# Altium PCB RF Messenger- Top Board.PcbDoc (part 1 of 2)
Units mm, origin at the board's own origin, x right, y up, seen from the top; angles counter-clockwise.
Board outline 60 x 85 mm, 2 copper layers (Top Layer, Bottom Layer), stack 1.569 mm thick; 38 components, 18 nets, 106 pads, 20 vias.
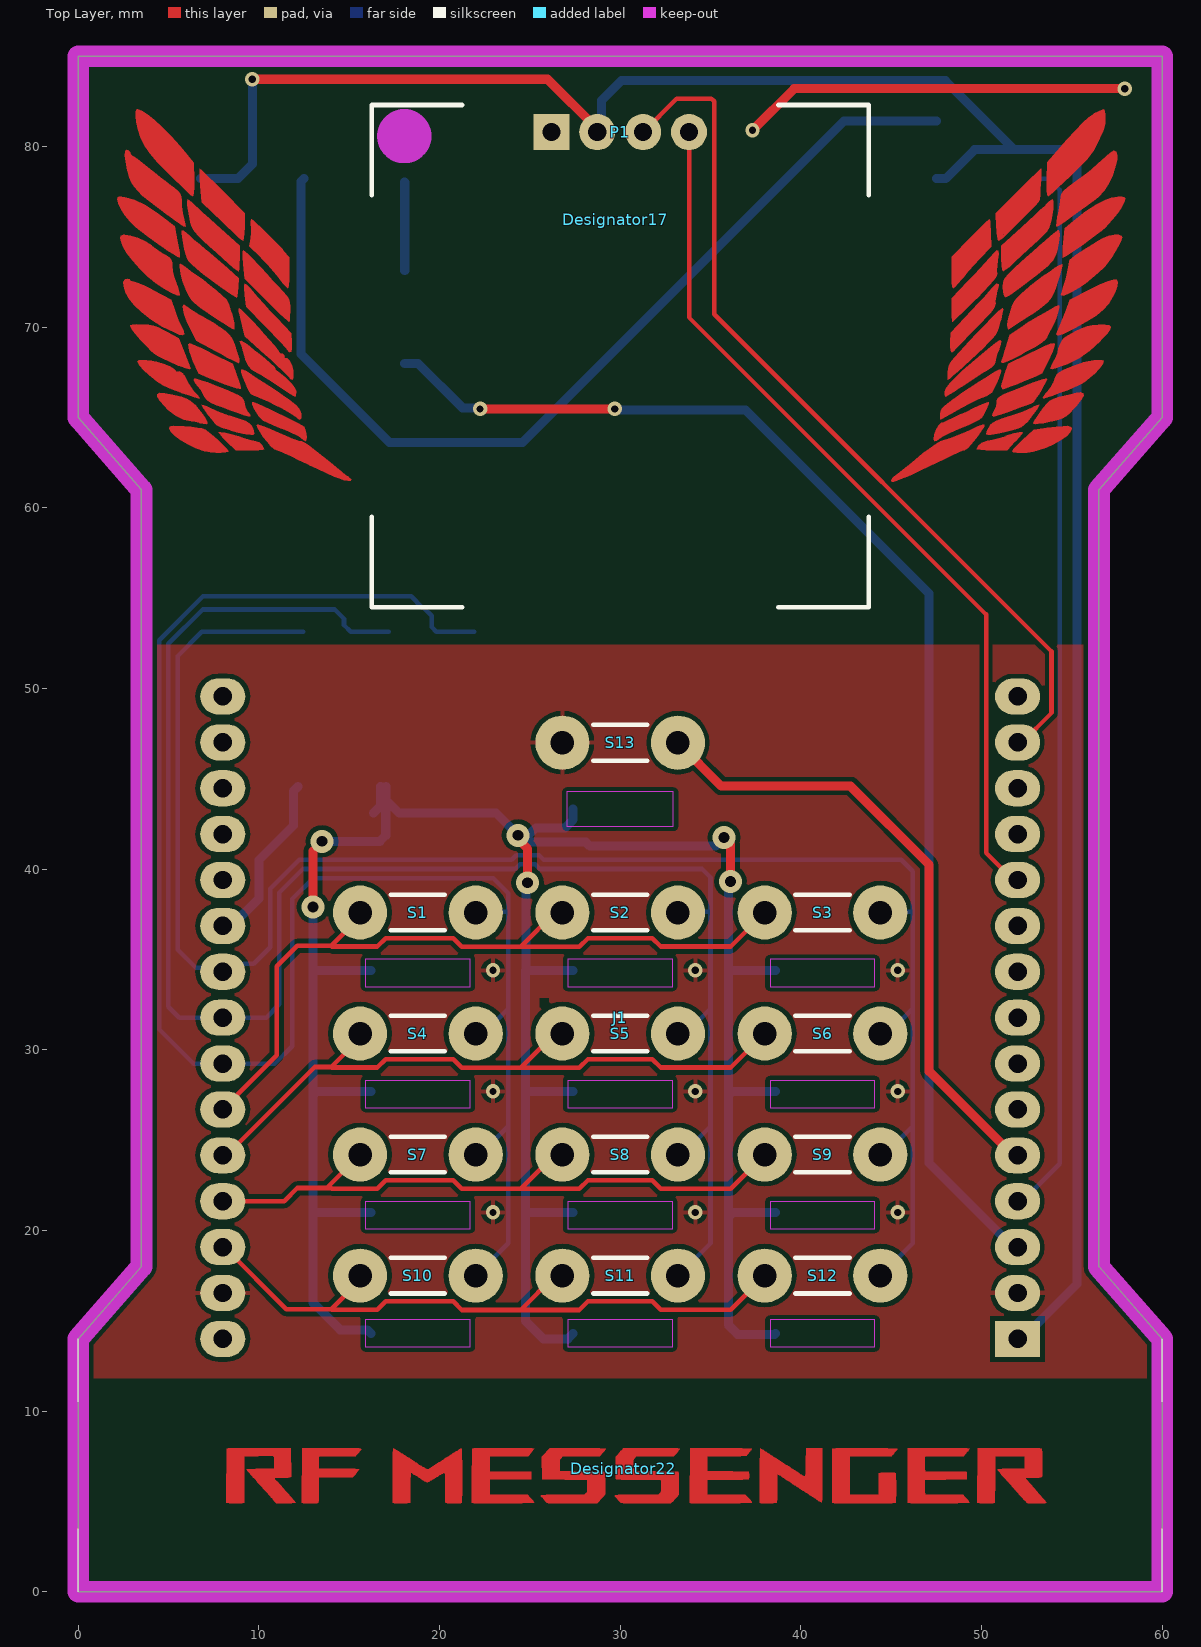
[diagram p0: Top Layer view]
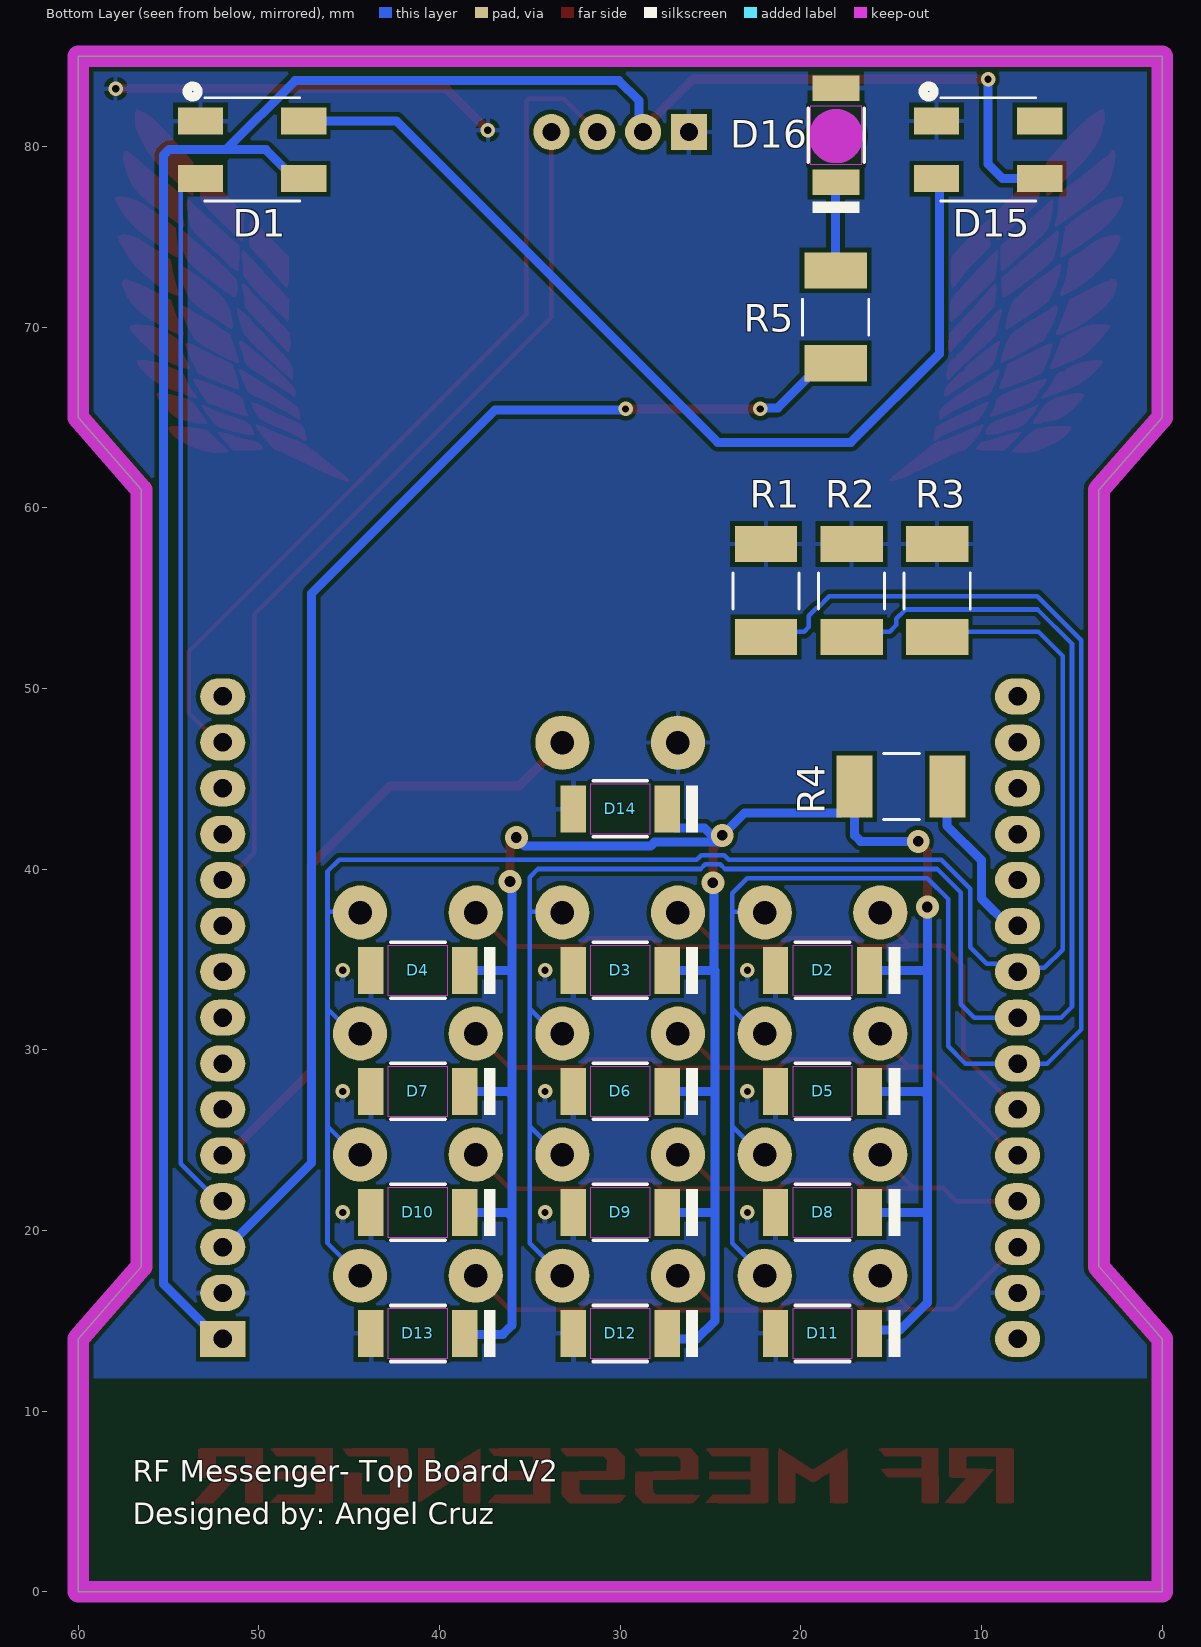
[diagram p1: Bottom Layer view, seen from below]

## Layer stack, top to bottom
Top Solder: solder mask 0.0254, SM-001, Dk 4
Top Layer: signal copper 0.035
Dielectric 1: core 1.4986, Core-043, Dk 4.3
Bottom Layer: signal copper 0.035
Bottom Solder: solder mask 0.0254, SM-001, Dk 4

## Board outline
0,0 0,14 3.5,18 3.5,61 0,65 0,85 60,85 60,65 56.5,61 56.5,18 60,14 60,0

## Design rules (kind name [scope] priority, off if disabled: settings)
Clearance [All] p1: gap=0.254 ignorepadtopadclearanceinfootprint=FALSE except(0: Arc-Hole Track-Hole SMDPad-Hole THPad-Hole Via-Hole Fill-Hole Poly-Hole Region-Hole Text-Hole)
PolygonConnect [All] p1: connectstyle=Relief reliefconductorwidth=0.254 reliefentries=4 polygonreliefangle="90 Angle" airgapwidth=0.254
RoutingVias "RoutingVias 2" [All] p1: holewidth=0.4 width=0.8 viastyle="Through Hole" minholewidth=0.4 minwidth=0.8 maxholewidth=0.711 maxwidth=1.27
RoutingVias [All] p2: holewidth=0.711 width=1.27 viastyle="Through Hole" minholewidth=0.711 minwidth=1.27 maxholewidth=0.711 maxwidth=1.27
SolderMaskExpansion [All] p1: expansion=0.102 istentingtop=FALSE
Width "Width 2" [All] p1: maxlimit=0.5 minlimit=0.25 preferedwidth=0.25
Width [All] p2: maxlimit=0.254 minlimit=0.254 preferedwidth=0.254
30 further rules are at their usual default settings.

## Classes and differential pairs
component class "RF Messenger- Top Board": D1 D2 D3 D4 D5 D6 D7 D8 D9 D10 D11 D12 D13 D14 D15 D16 J1 P1 R1 R2 R3 R4 R5 S1 S2 S3 S4 S5 S6 S7 S8 S9 S10 S11 S12 S13

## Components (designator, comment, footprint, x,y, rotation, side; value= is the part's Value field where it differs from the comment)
D1 "1655" LED_1655_ADA 50.371,79.821 r180 bottom
D2 "LED 2" XZDGK45WT-9 18.8,34.4 r0 bottom
D3 "LED 2" XZDGK45WT-9 30,34.4 r0 bottom
D4 "LED 2" XZDGK45WT-9 41.2,34.4 r0 bottom
D5 "LED 2" XZDGK45WT-9 18.8,27.7 r0 bottom
D6 "LED 2" XZDGK45WT-9 30,27.7 r0 bottom
D7 "LED 2" XZDGK45WT-9 41.2,27.7 r0 bottom
D8 "LED 2" XZDGK45WT-9 18.8,21 r0 bottom
D9 "LED 2" XZDGK45WT-9 30,21 r0 bottom
D10 "LED 2" XZDGK45WT-9 41.2,21 r0 bottom
D11 "LED 2" XZDGK45WT-9 18.8,14.3 r0 bottom
D12 "LED 2" XZDGK45WT-9 30,14.3 r0 bottom
D13 "LED 2" XZDGK45WT-9 41.2,14.3 r0 bottom
D14 "LED 2" XZDGK45WT-9 30,43.338 r0 bottom
D15 "1655" LED_1655_ADA 9.629,79.821 r180 bottom
D16 "LED 2" XZDGK45WT-9 18.05,80.625 r90 bottom
Designator17 "Comment" "Wings Artwork" 29.763,75.97 r0 top
Designator22 "Comment" "LOGO 4" 30.2,6.825 r0 top
J1 "Connector 2x15" "RF Messenger Connector Headers - duplicate" 52,14 r0 top locked
P1 "Header 4" OLED 26.19,80.8 r0 top locked
R1 "2k" "Resistor 1812_PAN-M" 21.93,55.42 r90 bottom
R2 "2k" "Resistor 1812_PAN-M" 17.193,55.42 r90 bottom
R3 "2k" "Resistor 1812_PAN-M" 12.456,55.42 r90 bottom
R4 "1K" "Resistor 1812_PAN-M" 14.45,44.575 r0 bottom
R5 "390" "Resistor 1812_PAN-M" 18.075,70.575 r90 bottom
S1 "Switch" "Tactile Switch (PTS636 SP50 LFS) THT" 18.8,37.6 r0 top
S2 "Switch" "Tactile Switch (PTS636 SP50 LFS) THT" 30,37.6 r0 top
S3 "Switch" "Tactile Switch (PTS636 SP50 LFS) THT" 41.2,37.6 r0 top
S4 "Switch" "Tactile Switch (PTS636 SP50 LFS) THT" 18.8,30.9 r0 top
S5 "Switch" "Tactile Switch (PTS636 SP50 LFS) THT" 30,30.9 r0 top
S6 "Switch" "Tactile Switch (PTS636 SP50 LFS) THT" 41.2,30.9 r0 top
S7 "Switch" "Tactile Switch (PTS636 SP50 LFS) THT" 18.8,24.2 r0 top
S8 "Switch" "Tactile Switch (PTS636 SP50 LFS) THT" 30,24.2 r0 top
S9 "Switch" "Tactile Switch (PTS636 SP50 LFS) THT" 41.2,24.2 r0 top
S10 "Switch" "Tactile Switch (PTS636 SP50 LFS) THT" 18.8,17.5 r0 top
S11 "Switch" "Tactile Switch (PTS636 SP50 LFS) THT" 30,17.5 r0 top
S12 "Switch" "Tactile Switch (PTS636 SP50 LFS) THT" 41.2,17.5 r0 top
S13 "Switch" "Tactile Switch (PTS636 SP50 LFS) THT" 30,47 r180 top

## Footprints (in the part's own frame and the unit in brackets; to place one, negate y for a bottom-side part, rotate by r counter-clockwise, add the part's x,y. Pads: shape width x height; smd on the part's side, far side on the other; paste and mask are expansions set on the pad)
LED_1655_ADA [mm]
  rect 2.5x1.5 smd paste+0: 1(-2.857,1.6) 2(-2.857,-1.6) 3(2.857,-1.6) 4(2.857,1.6)
  silkscreen extent -3.6,-2.83 2.63,3.52
"LOGO 4" [mm]
  Top Layer region: 22.245,1.118 22.469,1.117 22.657,1.116 22.81,1.114 22.932,1.112 23.023,1.109 23.085,1.105 23.119,1.101 23.128,1.098 23.135,1.084 23.142,1.055 23.147,1.006 23.15,0.935 23.153,0.836 23.155,0.706 23.156,0.542 23.156,0.34 23.156,0.316 23.156,-0.442 23.109,-0.475 23.085,-0.487 23.049,-0.496 22.993,-0.502 22.912,-0.505 22.801,-0.507 22.654,-0.508 22.512,-0.508 22.406,-0.51 22.333,-0.513 22.285,-0.517 22.259,-0.524 22.248,-0.534 22.246,-0.541 22.26,-0.585 22.273,-0.602 22.302,-0.634 22.353,-0.69 22.419,-0.765 22.494,-0.849 22.572,-0.937 22.645,-1.021 22.669,-1.048 22.737,-1.125 22.808,-1.205 22.866,-1.27 22.976,-1.391 23.08,-1.508 23.175,-1.616 23.256,-1.711 23.322,-1.789 23.367,-1.845 23.388,-1.876 23.389,-1.879 23.371,-1.897 23.326,-1.912 23.323,-1.913 23.278,-1.918 23.199,-1.921 23.095,-1.924 22.974,-1.925 22.845,-1.926 22.716,-1.925 22.594,-1.924 22.489,-1.921 22.409,-1.918 22.362,-1.913 22.36,-1.913 22.309,-1.886 22.238,-1.824 22.151,-1.73 22.083,-1.653 22.02,-1.581 21.97,-1.525 21.95,-1.502 21.897,-1.443 21.845,-1.383 21.805,-1.338 21.748,-1.275 21.685,-1.205 21.676,-1.195 21.6,-1.112 21.516,-1.017 21.442,-0.933 21.385,-0.868 21.338,-0.814 21.308,-0.78 21.303,-0.775 21.278,-0.747 21.23,-0.695 21.166,-0.624 21.092,-0.54 21.012,-0.452 20.934,-0.364 20.863,-0.283 20.804,-0.217 20.78,-0.189 20.729,-0.129 20.703,-0.091 20.698,-0.068 20.711,-0.051 20.716,-0.048 20.737,-0.04 20.78,-0.034 20.849,-0.029 20.946,-0.026 21.076,-0.023 21.241,-0.022 21.444,-0.021 21.478,-0.021 22.205,-0.021 22.199,0.323 22.193,0.667 20.563,0.667 20.553,-0.613 20.542,-1.893 20.489,-1.907 20.446,-1.913 20.371,-1.918 20.271,-1.921 20.157,-1.922 20.035,-1.922 19.916,-1.921 19.806,-1.918 19.715,-1.914 19.652,-1.909 19.627,-1.904 19.579,-1.885 19.59,1.111 21.344,1.117 21.685,1.118 21.985,1.118
  Top Layer region: 18.281,1.118 18.493,1.117 18.671,1.116 18.817,1.115 18.932,1.113 19.02,1.11 19.082,1.106 19.12,1.102 19.136,1.098 19.137,1.097 19.14,1.082 19.131,1.059 19.104,1.023 19.056,0.967 18.986,0.891 18.955,0.855 18.911,0.8 18.884,0.767 18.814,0.677 17.769,0.677 17.562,0.677 17.367,0.676 17.189,0.675 17.032,0.674 16.899,0.672 16.796,0.67 16.725,0.667 16.693,0.665 16.692,0.664 16.679,0.654 16.67,0.632 16.664,0.59 16.66,0.523 16.659,0.426 16.658,0.295 16.659,0.173 16.663,0.062 16.668,-0.029 16.674,-0.092 16.679,-0.115 16.699,-0.169 17.817,-0.17 18.031,-0.17 18.232,-0.171 18.417,-0.173 18.582,-0.175 18.722,-0.177 18.834,-0.18 18.913,-0.183 18.955,-0.186 18.961,-0.187 18.975,-0.21 18.982,-0.261 18.983,-0.346 18.982,-0.404 18.976,-0.603 17.822,-0.614 17.606,-0.616 17.402,-0.619 17.215,-0.621 17.049,-0.623 16.908,-0.625 16.795,-0.627 16.715,-0.628 16.671,-0.63 16.663,-0.63 16.659,-0.655 16.657,-0.713 16.656,-0.797 16.657,-0.899 16.658,-1.01 16.661,-1.123 16.665,-1.228 16.669,-1.318 16.674,-1.384 16.679,-1.418 16.68,-1.42 16.686,-1.429 16.697,-1.437 16.715,-1.443 16.744,-1.448 16.788,-1.452 16.851,-1.455 16.935,-1.457 17.045,-1.459 17.184,-1.46 17.356,-1.46 17.563,-1.46 17.741,-1.461 18.78,-1.461 18.868,-1.551 18.977,-1.667 19.056,-1.757 19.108,-1.823 19.134,-1.867 19.136,-1.891 19.134,-1.893 19.109,-1.897 19.046,-1.901 18.949,-1.904 18.821,-1.907 18.666,-1.91 18.489,-1.913 18.293,-1.915 18.081,-1.917 17.859,-1.918 17.63,-1.92 17.398,-1.92 17.166,-1.921 16.939,-1.921 16.721,-1.921 16.515,-1.92 16.326,-1.919 16.157,-1.917 16.012,-1.915 15.895,-1.913 15.811,-1.91 15.762,-1.906 15.753,-1.904 15.705,-1.885 15.716,1.111 17.419,1.117 17.746,1.118 18.032,1.118
  Top Layer region: 13.305,1.119 13.544,1.118 13.779,1.117 14.009,1.116 14.227,1.114 14.432,1.111 14.618,1.109 14.782,1.106 14.921,1.102 15.03,1.098 15.106,1.094 15.145,1.089 15.149,1.087 15.143,1.053 15.13,1.034 15.103,1.004 15.059,0.952 15.008,0.889 14.953,0.823 14.902,0.763 14.868,0.725 14.823,0.678 13.671,0.672 12.52,0.667 12.52,-1.45 13.271,-1.456 13.448,-1.457 13.612,-1.457 13.759,-1.457 13.883,-1.456 13.98,-1.454 14.045,-1.452 14.071,-1.45 14.118,-1.439 14.118,-0.274 14.172,-0.253 14.215,-0.245 14.289,-0.239 14.386,-0.235 14.498,-0.233 14.618,-0.232 14.737,-0.234 14.847,-0.237 14.94,-0.242 15.008,-0.248 15.043,-0.257 15.045,-0.258 15.052,-0.286 15.058,-0.35 15.063,-0.445 15.067,-0.565 15.07,-0.705 15.072,-0.858 15.073,-1.019 15.072,-1.182 15.071,-1.341 15.069,-1.492 15.066,-1.627 15.062,-1.741 15.057,-1.829 15.051,-1.884 15.045,-1.901 15.02,-1.905 14.957,-1.909 14.859,-1.912 14.731,-1.915 14.575,-1.918 14.397,-1.92 14.2,-1.922 13.987,-1.924 13.763,-1.925 13.531,-1.925 13.296,-1.926 13.062,-1.926 12.831,-1.925 12.609,-1.925 12.398,-1.923 12.203,-1.922 12.028,-1.92 11.876,-1.917 11.752,-1.914 11.659,-1.911 11.601,-1.907 11.583,-1.904 11.536,-1.885 11.536,-0.408 11.536,-0.161 11.537,0.073 11.538,0.292 11.54,0.492 11.542,0.669 11.544,0.82 11.546,0.942 11.549,1.03 11.551,1.083 11.553,1.095 11.577,1.1 11.639,1.104 11.736,1.108 11.863,1.111 12.018,1.114 12.196,1.116 12.394,1.117 12.607,1.118 12.832,1.119 13.066,1.119
  Top Layer region: 159 vertices and 0 holes, not listed, extent 7.535,-1.92 10.982,1.111
  Top Layer region: 5.733,1.111 6.049,1.11 6.322,1.109 6.554,1.107 6.744,1.105 6.891,1.102 6.997,1.098 7.061,1.094 7.084,1.09 7.084,1.09 7.075,1.062 7.046,1.019 7.033,1.004 6.987,0.952 6.932,0.887 6.876,0.82 6.828,0.76 6.796,0.719 6.79,0.711 6.767,0.705 6.708,0.699 6.61,0.694 6.473,0.69 6.297,0.686 6.08,0.682 5.823,0.679 5.7,0.677 4.625,0.667 4.625,-0.159 5.755,-0.164 6.034,-0.166 6.271,-0.168 6.469,-0.171 6.629,-0.174 6.752,-0.178 6.839,-0.183 6.893,-0.188 6.914,-0.193 6.93,-0.227 6.941,-0.288 6.945,-0.366 6.944,-0.448 6.937,-0.522 6.925,-0.577 6.909,-0.601 6.882,-0.603 6.817,-0.606 6.717,-0.608 6.588,-0.61 6.432,-0.611 6.255,-0.613 6.059,-0.614 5.85,-0.614 5.771,-0.614 5.559,-0.615 5.358,-0.616 5.175,-0.617 5.011,-0.619 4.873,-0.621 4.763,-0.624 4.686,-0.627 4.645,-0.63 4.64,-0.632 4.63,-0.648 4.624,-0.687 4.619,-0.752 4.618,-0.848 4.618,-0.98 4.619,-1.049 4.625,-1.45 5.675,-1.455 6.726,-1.461 6.801,-1.54 6.909,-1.655 6.99,-1.743 7.045,-1.808 7.078,-1.853 7.091,-1.881 7.088,-1.894 7.065,-1.897 7.003,-1.9 6.907,-1.903 6.78,-1.905 6.626,-1.908 6.45,-1.91 6.254,-1.912 6.044,-1.914 5.822,-1.916 5.594,-1.918 5.361,-1.919 5.13,-1.92 4.903,-1.92 4.685,-1.921 4.478,-1.921 4.289,-1.92 4.119,-1.92 3.973,-1.919 3.855,-1.917 3.769,-1.915 3.719,-1.913 3.709,-1.911 3.662,-1.902 3.672,1.111 5.375,1.111
  Top Layer region: 1.84,1.122 2.106,1.121 2.334,1.12 2.527,1.119 2.687,1.118 2.817,1.116 2.919,1.113 2.995,1.11 3.049,1.106 3.081,1.102 3.095,1.097 3.096,1.095 3.088,1.065 3.053,1.01 2.997,0.938 2.925,0.854 2.844,0.767 2.756,0.677 0.702,0.677 0.615,0.573 0.528,0.469 0.534,0.155 0.54,-0.159 1.765,-0.164 2.055,-0.166 2.303,-0.168 2.512,-0.17 2.683,-0.173 2.817,-0.177 2.917,-0.181 2.982,-0.186 3.015,-0.191 3.02,-0.193 3.028,-0.209 3.035,-0.241 3.04,-0.295 3.044,-0.375 3.046,-0.484 3.048,-0.627 3.048,-0.808 3.048,-0.83 3.048,-1.443 2.947,-1.563 2.879,-1.642 2.799,-1.73 2.729,-1.804 2.61,-1.926 1.258,-1.925 1.021,-1.924 0.797,-1.923 0.587,-1.922 0.398,-1.92 0.231,-1.918 0.09,-1.915 -0.02,-1.913 -0.096,-1.91 -0.134,-1.907 -0.138,-1.906 -0.17,-1.883 -0.221,-1.836 -0.282,-1.773 -0.307,-1.745 -0.369,-1.676 -0.424,-1.615 -0.464,-1.571 -0.473,-1.561 -0.492,-1.54 -0.505,-1.523 -0.51,-1.508 -0.502,-1.495 -0.48,-1.485 -0.44,-1.477 -0.379,-1.471 -0.294,-1.467 -0.183,-1.464 -0.043,-1.462 0.13,-1.46 0.338,-1.46 0.585,-1.459 0.693,-1.459 0.913,-1.458 1.121,-1.457 1.314,-1.456 1.486,-1.454 1.634,-1.452 1.754,-1.45 1.843,-1.448 1.895,-1.445 1.909,-1.443 1.942,-1.419 1.987,-1.373 2.009,-1.346 2.074,-1.264 2.074,-0.952 2.074,-0.828 2.071,-0.741 2.067,-0.683 2.06,-0.648 2.048,-0.631 2.041,-0.627 2.014,-0.624 1.949,-0.622 1.849,-0.62 1.718,-0.618 1.561,-0.617 1.381,-0.615 1.182,-0.615 0.967,-0.614 0.794,-0.614 0.535,-0.614 0.315,-0.613 0.132,-0.613 -0.02,-0.612 -0.141,-0.61 -0.236,-0.608 -0.308,-0.605 -0.36,-0.601 -0.396,-0.597 -0.417,-0.592 -0.428,-0.585 -0.432,-0.58 -0.435,-0.551 -0.438,-0.485 -0.441,-0.389 -0.443,-0.267 -0.444,-0.126 -0.444,0.029 -0.444,0.049 -0.444,0.646 -0.375,0.721 -0.321,0.782 -0.27,0.843 -0.257,0.859 -0.215,0.908 -0.159,0.972 -0.113,1.021 -0.018,1.122 1.534,1.122
  Top Layer region: -2.557,1.117 -2.263,1.116 -2.009,1.115 -1.791,1.113 -1.608,1.112 -1.455,1.111 -1.33,1.109 -1.231,1.107 -1.154,1.104 -1.096,1.101 -1.056,1.097 -1.029,1.092 -1.014,1.087 -1.007,1.081 -1.005,1.074 -1.019,1.044 -1.055,0.991 -1.109,0.923 -1.164,0.858 -1.323,0.679 -2.353,0.678 -3.383,0.677 -3.47,0.577 -3.556,0.476 -3.551,0.159 -3.545,-0.159 -2.32,-0.164 -2.03,-0.166 -1.782,-0.168 -1.573,-0.17 -1.402,-0.173 -1.268,-0.177 -1.169,-0.181 -1.103,-0.186 -1.07,-0.191 -1.066,-0.193 -1.057,-0.209 -1.05,-0.241 -1.045,-0.295 -1.041,-0.375 -1.039,-0.485 -1.038,-0.628 -1.037,-0.809 -1.037,-0.827 -1.037,-1.437 -1.143,-1.564 -1.215,-1.648 -1.297,-1.74 -1.361,-1.809 -1.474,-1.926 -2.827,-1.924 -3.064,-1.923 -3.289,-1.923 -3.498,-1.921 -3.688,-1.92 -3.855,-1.918 -3.996,-1.916 -4.106,-1.914 -4.182,-1.911 -4.221,-1.909 -4.224,-1.908 -4.258,-1.886 -4.31,-1.841 -4.368,-1.781 -4.38,-1.767 -4.441,-1.698 -4.499,-1.633 -4.541,-1.586 -4.545,-1.582 -4.567,-1.556 -4.585,-1.535 -4.594,-1.517 -4.591,-1.502 -4.574,-1.49 -4.54,-1.481 -4.486,-1.473 -4.408,-1.468 -4.305,-1.464 -4.173,-1.462 -4.009,-1.461 -3.811,-1.46 -3.574,-1.46 -3.403,-1.46 -3.183,-1.46 -2.976,-1.459 -2.784,-1.458 -2.612,-1.457 -2.464,-1.455 -2.344,-1.453 -2.255,-1.451 -2.203,-1.449 -2.191,-1.447 -2.152,-1.424 -2.103,-1.38 -2.085,-1.359 -2.021,-1.284 -2.015,-0.959 -2.013,-0.847 -2.012,-0.751 -2.012,-0.679 -2.013,-0.637 -2.015,-0.63 -2.036,-0.629 -2.097,-0.628 -2.192,-0.626 -2.319,-0.625 -2.473,-0.623 -2.65,-0.621 -2.848,-0.618 -3.062,-0.616 -3.27,-0.614 -4.519,-0.603 -4.53,0.646 -4.421,0.773 -4.35,0.854 -4.273,0.942 -4.211,1.011 -4.109,1.122
  Top Layer region: -6.331,1.122 -6.022,1.121 -5.752,1.119 -5.52,1.118 -5.328,1.115 -5.176,1.113 -5.064,1.109 -4.993,1.105 -4.964,1.101 -4.964,1.101 -4.972,1.078 -5.003,1.03 -5.054,0.964 -5.118,0.887 -5.125,0.879 -5.3,0.678 -6.36,0.672 -7.419,0.667 -7.419,-0.159 -6.276,-0.17 -6.06,-0.172 -5.857,-0.174 -5.672,-0.176 -5.507,-0.178 -5.367,-0.18 -5.255,-0.182 -5.176,-0.184 -5.133,-0.185 -5.127,-0.186 -5.125,-0.207 -5.124,-0.262 -5.125,-0.341 -5.127,-0.397 -5.133,-0.603 -7.419,-0.624 -7.419,-1.45 -5.318,-1.461 -5.199,-1.593 -5.134,-1.665 -5.07,-1.735 -5.019,-1.789 -5.013,-1.794 -4.973,-1.841 -4.962,-1.871 -4.972,-1.89 -4.997,-1.894 -5.06,-1.898 -5.158,-1.902 -5.286,-1.906 -5.441,-1.909 -5.619,-1.912 -5.816,-1.914 -6.027,-1.917 -6.25,-1.918 -6.479,-1.92 -6.712,-1.921 -6.944,-1.922 -7.171,-1.922 -7.389,-1.922 -7.595,-1.921 -7.784,-1.92 -7.953,-1.918 -8.098,-1.916 -8.214,-1.914 -8.299,-1.91 -8.347,-1.906 -8.356,-1.905 -8.403,-1.885 -8.403,-0.415 -8.403,-0.169 -8.402,0.065 -8.402,0.284 -8.401,0.484 -8.399,0.661 -8.398,0.813 -8.396,0.935 -8.394,1.023 -8.392,1.076 -8.39,1.088 -8.385,1.094 -8.372,1.1 -8.348,1.104 -8.312,1.108 -8.26,1.112 -8.189,1.114 -8.098,1.117 -7.982,1.118 -7.84,1.12 -7.669,1.121 -7.466,1.121 -7.229,1.122 -6.954,1.122 -6.677,1.122
  Top Layer region: 209 vertices and 0 holes, not listed, extent -12.785,-1.926 -8.954,1.114
  Top Layer region: -14.98,1.119 -14.844,1.117 -14.735,1.113 -14.651,1.107 -14.591,1.099 -14.552,1.088 -14.53,1.074 -14.524,1.057 -14.532,1.037 -14.551,1.012 -14.578,0.983 -14.612,0.949 -14.649,0.911 -14.65,0.91 -14.712,0.842 -14.766,0.78 -14.803,0.735 -14.81,0.725 -14.843,0.677 -15.819,0.677 -16.02,0.677 -16.209,0.676 -16.382,0.675 -16.534,0.673 -16.66,0.671 -16.757,0.669 -16.82,0.666 -16.843,0.664 -16.862,0.658 -16.874,0.646 -16.883,0.622 -16.888,0.579 -16.89,0.511 -16.891,0.412 -16.891,0.328 -16.89,0.202 -16.888,0.112 -16.884,0.052 -16.877,0.016 -16.866,-0.003 -16.858,-0.008 -16.83,-0.011 -16.765,-0.013 -16.666,-0.015 -16.536,-0.017 -16.381,-0.019 -16.204,-0.02 -16.01,-0.021 -15.802,-0.021 -15.746,-0.021 -15.501,-0.021 -15.295,-0.022 -15.125,-0.023 -14.987,-0.024 -14.879,-0.026 -14.796,-0.029 -14.736,-0.032 -14.695,-0.037 -14.67,-0.042 -14.658,-0.049 -14.655,-0.052 -14.664,-0.08 -14.696,-0.129 -14.745,-0.194 -14.804,-0.266 -14.868,-0.337 -14.928,-0.4 -14.98,-0.448 -15.015,-0.472 -15.018,-0.473 -15.047,-0.476 -15.115,-0.479 -15.215,-0.481 -15.344,-0.483 -15.497,-0.485 -15.67,-0.486 -15.857,-0.486 -15.976,-0.487 -16.891,-0.487 -16.891,-1.185 -16.891,-1.375 -16.892,-1.527 -16.893,-1.646 -16.895,-1.736 -16.898,-1.801 -16.902,-1.846 -16.908,-1.874 -16.916,-1.891 -16.926,-1.901 -16.932,-1.904 -16.967,-1.912 -17.036,-1.917 -17.13,-1.922 -17.241,-1.924 -17.36,-1.925 -17.479,-1.924 -17.589,-1.921 -17.681,-1.916 -17.747,-1.91 -17.775,-1.904 -17.823,-1.885 -17.812,1.111 -16.166,1.117 -15.854,1.118 -15.582,1.119 -15.347,1.12 -15.147,1.12
  Top Layer region: -20.824,1.118 -20.54,1.118 -20.217,1.117 -20.192,1.117 -18.426,1.111 -18.414,-0.467 -18.469,-0.487 -18.507,-0.494 -18.58,-0.5 -18.679,-0.504 -18.797,-0.507 -18.924,-0.508 -19.064,-0.508 -19.167,-0.509 -19.238,-0.512 -19.284,-0.516 -19.31,-0.523 -19.322,-0.533 -19.325,-0.546 -19.325,-0.549 -19.318,-0.586 -19.309,-0.596 -19.286,-0.616 -19.238,-0.665 -19.167,-0.742 -19.075,-0.843 -18.966,-0.966 -18.902,-1.038 -18.825,-1.125 -18.741,-1.219 -18.666,-1.303 -18.648,-1.323 -18.559,-1.422 -18.466,-1.527 -18.375,-1.63 -18.294,-1.722 -18.232,-1.794 -18.215,-1.815 -18.18,-1.859 -18.172,-1.882 -18.187,-1.896 -18.196,-1.9 -18.228,-1.904 -18.295,-1.908 -18.392,-1.911 -18.512,-1.914 -18.649,-1.915 -18.739,-1.916 -19.243,-1.916 -19.339,-1.81 -19.405,-1.736 -19.473,-1.658 -19.513,-1.61 -19.573,-1.54 -19.637,-1.469 -19.664,-1.44 -19.745,-1.355 -19.83,-1.261 -19.91,-1.172 -19.972,-1.099 -19.982,-1.088 -20.027,-1.035 -20.092,-0.96 -20.168,-0.873 -20.249,-0.783 -20.324,-0.7 -20.383,-0.636 -20.436,-0.578 -20.502,-0.505 -20.563,-0.435 -20.636,-0.353 -20.718,-0.261 -20.779,-0.194 -20.84,-0.121 -20.869,-0.073 -20.868,-0.053 -20.841,-0.047 -20.775,-0.041 -20.673,-0.036 -20.538,-0.031 -20.372,-0.026 -20.18,-0.022 -20.102,-0.021 -19.357,-0.011 -19.351,0.322 -19.349,0.448 -19.349,0.537 -19.35,0.597 -19.355,0.633 -19.364,0.653 -19.378,0.662 -19.393,0.667 -19.425,0.669 -19.494,0.671 -19.595,0.673 -19.724,0.674 -19.874,0.674 -20.042,0.674 -20.221,0.673 -20.225,0.673 -21.008,0.667 -21.019,-1.885 -21.073,-1.906 -21.113,-1.913 -21.187,-1.918 -21.286,-1.922 -21.401,-1.924 -21.523,-1.924 -21.645,-1.923 -21.757,-1.92 -21.85,-1.916 -21.917,-1.91 -21.945,-1.904 -21.992,-1.885 -21.992,-0.408 -21.992,-0.161 -21.991,0.073 -21.99,0.292 -21.988,0.492 -21.986,0.669 -21.984,0.82 -21.982,0.942 -21.979,1.03 -21.977,1.083 -21.975,1.095 -21.964,1.1 -21.936,1.105 -21.888,1.108 -21.819,1.111 -21.726,1.114 -21.608,1.116 -21.46,1.117 -21.282,1.118 -21.071,1.118
OLED [mm]
  rect 2x2 hole 1: 1(0,0)
  round 2 hole 1: 2(2.54,0) 3(5.08,0) 4(7.62,0)
  silkscreen extent -9.94,-26.3 17.56,1.5
"Resistor 1812_PAN-M" [mm]
  rect 2x3.454 smd paste+0 mask+0: 1(-2.573,0) 2(2.573,0)
  silkscreen extent -1.02,-1.83 0.98,1.83, body extent 0,0 0.25,0.25, height 0.25
"RF Messenger Connector Headers - duplicate" [mm] "Connector headers to connect top and bottom boards"
  rect 2.5x2 hole 1.02: 1(0,0)
  oval 2.5x2 hole 1.02: 2(0,2.54) 3(0,5.08) 4(0,7.62) 5(0,10.16) 6(0,12.7) 7(0,15.24) 8(0,17.78) 9(0,20.32) 10(0,22.86) 11(0,25.4) 12(0,27.94) 13(0,30.48) 14(0,33.02) 15(0,35.56) 16(-44,35.56) 17(-44,33.02) 18(-44,30.48) 19(-44,27.94) 20(-44,25.4) 21(-44,22.86) 22(-44,20.32) 23(-44,17.78) 24(-44,15.24) 25(-44,12.7) 26(-44,10.16) 27(-44,7.62) 28(-44,5.08) 29(-44,2.54) 30(-44,0)
"Tactile Switch (PTS636 SP50 LFS) THT" [mm] "Through hole tactile switch"
  round 3 hole 1.3: 1(-3.2,0) 2(3.2,0)
  silkscreen extent -1.5,-0.99 1.5,0.99
"Wings Artwork" [mm]
  Top Layer circle w0.25: c-24.1,-8.675 r0.035
  Top Layer region: -25.625,-4.15 -25.45,-4.15 -25.45,-4.025 -25.625,-4.025
  Top Layer region: -25.85,-6.05 -25.725,-6.05 -25.725,-5.9 -25.85,-5.9
  Top Layer region: -25.925,-1.525 -25.8,-1.525 -25.8,-1.425 -25.925,-1.425
  Top Layer region: -21.6,-4.675 -21.5,-4.675 -21.5,-4.55 -21.6,-4.55
  Top Layer region: -21.95,-4.35 -21.825,-4.35 -21.825,-4.225 -21.95,-4.225
  Top Layer region: -20.15,-4.35 -19.975,-4.35 -19.975,-4.15 -20.15,-4.15
  Top Layer region: -20.25,-11.6 -20.15,-11.6 -20.15,-11.5 -20.25,-11.5
  Top Layer region: -15.1,-14.325 -14.975,-14.325 -14.975,-14.2 -15.1,-14.2
  Top Layer region: 21.4,-0.85 21.525,-0.85 21.525,-0.75 21.4,-0.75
  Top Layer region: -27.351,1.253 -27.199,1.233 -26.673,1.093 -26.082,0.813 -25.443,0.403 -25.104,0.146 -24.426,-0.392 -24.278,-1.155 -24.199,-1.57 -24.153,-1.847 -24.136,-2.011 -24.148,-2.091 -24.184,-2.112 -24.194,-2.111 -24.284,-2.064 -24.485,-1.94 -24.77,-1.756 -25.108,-1.53 -25.162,-1.493 -25.566,-1.212 -25.974,-0.914 -26.335,-0.636 -26.575,-0.44 -26.895,-0.123 -27.183,0.231 -27.413,0.584 -27.561,0.899 -27.601,1.099 -27.588,1.212 -27.519,1.258
  Top Layer region: -26.855,-0.897 -26.459,-1.029 -26.056,-1.22 -25.705,-1.444 -25.684,-1.46 -25.386,-1.678 -25.054,-1.899 -24.944,-1.966 -24.716,-2.111 -24.6,-2.233 -24.559,-2.393 -24.553,-2.578 -24.522,-2.86 -24.441,-3.214 -24.342,-3.522 -24.237,-3.81 -24.161,-4.038 -24.13,-4.156 -24.13,-4.159 -24.172,-4.225 -24.306,-4.207 -24.547,-4.101 -24.907,-3.9 -24.989,-3.851 -25.462,-3.533 -25.928,-3.152 -26.367,-2.733 -26.757,-2.3 -27.077,-1.877 -27.305,-1.489 -27.308,-1.482 -27.422,-1.16 -27.432,-1.054 -27.403,-0.905 -27.283,-0.851 -27.181,-0.847 hole: -25.866,-1.439 -25.908,-1.482 -25.866,-1.524 -25.823,-1.482
  Top Layer region: -26.903,-3.327 -26.877,-3.379 -26.852,-3.428 -26.776,-3.424 -26.649,-3.449 -26.406,-3.542 -26.079,-3.689 -25.702,-3.875 -25.618,-3.918 -24.607,-4.445 -24.424,-4.995 -24.297,-5.345 -24.157,-5.689 -24.058,-5.902 -23.921,-6.197 -23.886,-6.368 -23.964,-6.425 -24.167,-6.378 -24.46,-6.258 -25.107,-5.932 -25.709,-5.558 -26.24,-5.155 -26.675,-4.744 -26.989,-4.344 -27.112,-4.106 -27.123,-4.083 -27.242,-3.708 -27.259,-3.46 -27.172,-3.329 -27.046,-3.302 hole: -25.527,-4.064 -25.569,-4.106 -25.527,-4.149 -25.485,-4.106
  Top Layer region: -26.996,3.831 -26.89,3.719 -26.847,3.598 -26.779,3.516 -26.762,3.514 -26.669,3.463 -26.476,3.324 -26.21,3.12 -25.91,2.879 -25.561,2.597 -25.218,2.326 -24.926,2.103 -24.76,1.982 -24.433,1.747 -24.224,1.568 -24.107,1.414 -24.056,1.249 -24.045,1.057 -24.026,0.726 -23.974,0.342 -23.904,-0.02 -23.83,-0.275 -23.815,-0.395 -23.846,-0.419 -23.938,-0.371 -24.138,-0.24 -24.418,-0.046 -24.751,0.192 -24.813,0.237 -25.395,0.665 -25.855,1.018 -26.209,1.315 -26.476,1.575 -26.672,1.818 -26.816,2.063 -26.924,2.33 -27.014,2.638 -27.037,2.727 -27.135,3.192 -27.174,3.548 -27.151,3.775 -27.103,3.846
  Top Layer region: -26.239,-5.822 -26.182,-5.824 -25.848,-5.845 -25.585,-5.891 -25.331,-5.98 -25.022,-6.133 -24.868,-6.216 -24.196,-6.584 -23.867,-7.419 -23.732,-7.763 -23.624,-8.043 -23.555,-8.224 -23.538,-8.276 -23.609,-8.299 -23.809,-8.25 -24.117,-8.136 -24.215,-8.096 -24.703,-7.885 -25.067,-7.717 -25.338,-7.572 -25.55,-7.432 -25.736,-7.276 -25.921,-7.092 -26.302,-6.685 -26.598,-6.344 -26.797,-6.082 -26.859,-5.969 -26.889,-5.914 -26.886,-5.861 -26.777,-5.835 -26.546,-5.821 hole: -25.781,-5.927 -25.823,-5.969 -25.781,-6.011 -25.739,-5.969
  Top Layer region: -26.25,6.02 -25.936,5.823 -25.551,5.514 -25.11,5.106 -24.627,4.613 -24.116,4.047 -23.72,3.579 -23.356,3.137 -23.341,2.204 -23.341,1.77 -23.357,1.464 -23.388,1.302 -23.41,1.28 -23.521,1.343 -23.683,1.484 -23.711,1.513 -23.849,1.65 -24.081,1.878 -24.378,2.167 -24.714,2.492 -24.854,2.626 -25.388,3.168 -25.797,3.653 -26.102,4.114 -26.324,4.581 -26.468,5.027 -26.546,5.394 -26.581,5.716 -26.57,5.957 -26.513,6.082 -26.479,6.092
  Top Layer region: -25.974,-7.797 -25.698,-7.825 -25.456,-7.871 -25.406,-7.886 -24.981,-8.034 -24.65,-8.172 -24.437,-8.291 -24.364,-8.38 -24.365,-8.385 -24.335,-8.438 -24.298,-8.423 -24.151,-8.42 -23.977,-8.528 -23.826,-8.708 -23.749,-8.892 -23.658,-9.101 -23.486,-9.354 -23.358,-9.503 -23.182,-9.7 -23.071,-9.848 -23.049,-9.902 -23.132,-9.895 -23.344,-9.839 -23.652,-9.744 -24.024,-9.618 -24.047,-9.61 -24.593,-9.404 -25.022,-9.204 -25.381,-8.986 -25.548,-8.864 -25.853,-8.611 -25.871,-8.594 -26.129,-8.348 -26.346,-8.108 -26.476,-7.92 -26.501,-7.845 -26.425,-7.805 -26.233,-7.79 hole: -24.003,-8.551 -24.045,-8.594 -24.003,-8.636 -23.961,-8.594
  Top Layer region: -24.96,-9.626 -24.522,-9.71 -24.415,-9.735 -24.032,-9.833 -23.763,-9.929 -23.557,-10.046 -23.36,-10.21 -23.298,-10.269 -23.083,-10.505 -22.877,-10.776 -22.712,-11.036 -22.617,-11.239 -22.606,-11.3 -22.676,-11.337 -22.841,-11.327 -23.038,-11.274 -23.072,-11.261 -23.278,-11.206 -23.517,-11.182 -23.929,-11.098 -24.369,-10.875 -24.803,-10.532 -24.977,-10.355 -25.246,-10.038 -25.384,-9.812 -25.386,-9.671 -25.246,-9.611
  Top Layer region: -24.263,-11.44 -23.893,-11.463 -23.51,-11.494 -23.168,-11.53 -22.919,-11.565 -22.842,-11.581 -22.706,-11.655 -22.499,-11.809 -22.253,-12.015 -21.997,-12.245 -21.76,-12.473 -21.575,-12.669 -21.469,-12.806 -21.46,-12.852 -21.593,-12.898 -21.84,-12.919 -22.147,-12.917 -22.462,-12.893 -22.731,-12.846 -22.775,-12.834 -23.244,-12.666 -23.692,-12.457 -24.091,-12.225 -24.415,-11.988 -24.634,-11.764 -24.722,-11.571 -24.723,-11.557 -24.709,-11.489 -24.649,-11.448 -24.51,-11.433
  Top Layer region: -24.004,-2.509 -23.851,-2.633 -23.678,-2.775 -23.424,-2.96 -23.212,-3.102 -22.845,-3.355 -22.472,-3.636 -22.12,-3.924 -21.814,-4.196 -21.58,-4.43 -21.445,-4.603 -21.421,-4.668 -21.383,-4.866 -21.306,-5.063 -21.234,-5.255 -21.173,-5.503 -21.131,-5.758 -21.114,-5.968 -21.131,-6.083 -21.147,-6.091 -21.249,-6.045 -21.438,-5.936 -21.548,-5.867 -22.115,-5.499 -22.56,-5.209 -22.901,-4.977 -23.156,-4.788 -23.344,-4.624 -23.353,-4.614 -23.484,-4.468 -23.594,-4.303 -23.608,-4.276 -23.693,-4.111 -23.799,-3.876 -23.865,-3.725 -23.969,-3.452 -24.056,-3.148 -24.119,-2.856 -24.15,-2.618 -24.14,-2.477 -24.115,-2.455 hole: -21.886,-4.233 -21.929,-4.276 -21.886,-4.318 -21.844,-4.276 hole: -21.548,-4.572 -21.59,-4.614 -21.548,-4.657 -21.505,-4.614
  Top Layer region: -23.928,-0.641 -23.762,-0.757 -23.599,-0.9 -23.36,-1.117 -23.047,-1.388 -22.72,-1.662 -22.648,-1.72 -22.29,-2.018 -21.886,-2.363 -21.514,-2.688 -21.463,-2.733 -20.87,-3.265 -20.896,-3.77 -20.919,-4.048 -20.952,-4.253 -20.981,-4.328 -21.064,-4.296 -21.259,-4.176 -21.546,-3.983 -21.902,-3.732 -22.305,-3.437 -22.329,-3.419 -22.835,-3.035 -23.215,-2.731 -23.482,-2.494 -23.652,-2.311 -23.737,-2.174 -23.814,-1.944 -23.89,-1.642 -23.957,-1.314 -24.006,-1.005 -24.03,-0.761 -24.02,-0.627 -24.015,-0.619
  Top Layer region: -23.808,-4.788 -23.637,-4.904 -23.588,-4.941 -23.356,-5.098 -23.059,-5.275 -22.902,-5.36 -22.621,-5.519 -22.273,-5.735 -21.93,-5.962 -21.896,-5.986 -21.598,-6.202 -21.403,-6.378 -21.27,-6.564 -21.156,-6.809 -21.105,-6.943 -20.947,-7.39 -20.859,-7.715 -20.841,-7.907 -20.882,-7.958 -20.978,-7.919 -21.195,-7.812 -21.505,-7.652 -21.88,-7.452 -22.089,-7.339 -23.222,-6.721 -23.59,-6.006 -23.762,-5.635 -23.887,-5.293 -23.959,-5.009 -23.968,-4.816 -23.908,-4.741 -23.905,-4.741
  Top Layer region: -23.611,1.047 -23.445,0.909 -23.308,0.783 -23.13,0.618 -22.856,0.367 -22.516,0.059 -22.139,-0.281 -21.901,-0.495 -20.828,-1.455 -20.828,-2.167 -20.836,-2.49 -20.856,-2.737 -20.886,-2.867 -20.899,-2.879 -20.981,-2.825 -21.168,-2.674 -21.436,-2.446 -21.766,-2.157 -22.105,-1.854 -22.484,-1.506 -22.828,-1.179 -23.114,-0.896 -23.317,-0.682 -23.405,-0.572 -23.476,-0.406 -23.55,-0.147 -23.62,0.164 -23.678,0.485 -23.717,0.775 -23.73,0.993 -23.709,1.097 -23.7,1.101
  Top Layer region: -23.492,-6.896 -23.261,-6.996 -22.937,-7.146 -22.55,-7.333 -22.352,-7.431 -21.209,-8.001 -20.985,-8.636 -20.879,-8.942 -20.797,-9.185 -20.755,-9.322 -20.752,-9.335 -20.768,-9.379 -20.847,-9.385 -21.01,-9.348 -21.277,-9.261 -21.668,-9.12 -21.969,-9.007 -22.36,-8.856 -22.697,-8.721 -22.945,-8.614 -23.072,-8.551 -23.077,-8.547 -23.152,-8.431 -23.261,-8.2 -23.386,-7.9 -23.507,-7.579 -23.606,-7.282 -23.658,-7.091 -23.669,-6.909 -23.602,-6.859
  Top Layer region: -23.22,-8.834 -22.972,-8.9 -22.595,-9.031 -22.077,-9.227 -21.971,-9.267 -21.476,-9.462 -21.117,-9.613 -20.87,-9.737 -20.711,-9.849 -20.619,-9.965 -20.568,-10.101 -20.544,-10.228 -20.479,-10.47 -20.385,-10.645 -20.363,-10.667 -20.232,-10.81 -20.242,-10.891 -20.374,-10.902 -20.61,-10.84 -20.743,-10.786 -20.967,-10.699 -21.29,-10.583 -21.648,-10.463 -21.717,-10.441 -22.136,-10.295 -22.426,-10.158 -22.627,-10.004 -22.776,-9.808 -22.838,-9.695 -22.989,-9.444 -23.168,-9.201 -23.313,-9.016 -23.378,-8.892 -23.351,-8.832
  Top Layer region: -22.957,2.737 -22.784,2.577 -22.53,2.333 -22.212,2.022 -21.849,1.663 -21.756,1.57 -20.532,0.346 -20.556,-0.42 -20.573,-0.756 -20.598,-1.017 -20.626,-1.164 -20.641,-1.184 -20.726,-1.128 -20.9,-0.983 -21.129,-0.774 -21.211,-0.697 -21.518,-0.406 -21.882,-0.06 -22.236,0.276 -22.327,0.362 -22.932,0.935 -23.004,1.865 -23.029,2.238 -23.041,2.54 -23.04,2.736 -23.028,2.794
  Top Layer region: -22.824,-10.283 -22.644,-10.357 -22.593,-10.383 -22.057,-10.63 -21.393,-10.862 -21.336,-10.88 -20.859,-11.032 -20.521,-11.162 -20.294,-11.286 -20.151,-11.421 -20.067,-11.585 -20.033,-11.705 -20.011,-11.871 -20.085,-11.926 -20.213,-11.926 -20.478,-11.904 -20.659,-11.88 -20.895,-11.826 -21.201,-11.737 -21.526,-11.631 -21.731,-11.557 -21.818,-11.525 -22.026,-11.436 -22.085,-11.401 -22.208,-11.278 -22.376,-11.079 -22.559,-10.842 -22.73,-10.607 -22.86,-10.411 -22.92,-10.292 -22.919,-10.276 hole: -20.193,-11.515 -20.235,-11.557 -20.193,-11.599 -20.151,-11.557
  Top Layer region: -21.625,-11.819 -21.287,-11.902 -20.879,-12.02 -20.574,-12.118 -20.284,-12.204 -20.034,-12.261 -19.923,-12.275 -19.749,-12.342 -19.578,-12.498 -19.479,-12.675 -19.473,-12.719 -19.552,-12.747 -19.762,-12.77 -20.068,-12.782 -20.256,-12.784 -21.04,-12.784 -21.532,-12.31 -21.754,-12.085 -21.911,-11.905 -21.977,-11.799 -21.975,-11.787 -21.865,-11.778
  Top Layer region: -20.762,-4.971 -20.591,-5.134 -20.353,-5.379 -20.071,-5.68 -19.764,-6.014 -19.456,-6.358 -19.166,-6.687 -18.916,-6.979 -18.728,-7.209 -18.622,-7.355 -18.608,-7.391 -18.579,-7.428 -18.554,-7.416 -18.447,-7.426 -18.355,-7.526 -18.339,-7.642 -18.352,-7.663 -18.357,-7.695 -18.321,-7.679 -18.184,-7.682 -18.047,-7.819 -17.932,-8.053 -17.861,-8.348 -17.852,-8.446 -17.851,-8.738 -17.9,-8.87 -18,-8.844 -18.13,-8.697 -18.236,-8.581 -18.447,-8.374 -18.737,-8.101 -19.083,-7.782 -19.402,-7.493 -20.537,-6.477 -20.683,-5.884 -20.764,-5.56 -20.835,-5.279 -20.881,-5.102 -20.881,-5.101 -20.89,-4.954 -20.845,-4.911
  Top Layer region: -20.533,-1.762 -20.357,-1.928 -20.113,-2.176 -19.821,-2.484 -19.665,-2.653 -19.324,-3.025 -18.988,-3.392 -18.69,-3.716 -18.464,-3.963 -18.416,-4.015 -18.22,-4.236 -18.106,-4.404 -18.052,-4.58 -18.035,-4.824 -18.034,-5.052 -18.042,-5.352 -18.063,-5.572 -18.094,-5.671 -18.099,-5.673 -18.176,-5.615 -18.352,-5.456 -18.61,-5.212 -18.928,-4.902 -19.289,-4.545 -19.347,-4.486 -20.532,-3.3 -20.617,-2.497 -20.654,-2.069 -20.657,-1.805 -20.626,-1.702 -20.617,-1.7
  Top Layer region: -20.443,-3.624 -20.279,-3.788 -20.073,-4.021 -20.024,-4.081 -19.799,-4.344 -19.496,-4.686 -19.151,-5.063 -18.805,-5.432 -18.783,-5.456 -17.966,-6.314 -17.937,-6.84 -17.936,-7.172 -17.98,-7.343 -18.071,-7.352 -18.211,-7.203 -18.23,-7.175 -18.331,-7.054 -18.529,-6.836 -18.801,-6.545 -19.125,-6.206 -19.411,-5.912 -20.46,-4.839 -20.541,-4.197 -20.544,-4.173 -20.578,-3.831 -20.575,-3.622 -20.535,-3.56 hole: -20.137,-4.173 -20.116,-4.22 -20.031,-4.311 -19.982,-4.292 -19.981,-4.281 -20.041,-4.209 -20.079,-4.183
  Top Layer region: -20.591,-6.799 -20.497,-6.869 -20.281,-7.037 -20.006,-7.246 -19.846,-7.366 -19.434,-7.685 -19.12,-7.953 -18.919,-8.157 -18.841,-8.285 -18.845,-8.309 -18.839,-8.366 -18.813,-8.363 -18.719,-8.407 -18.539,-8.544 -18.304,-8.748 -18.214,-8.832 -17.94,-9.107 -17.779,-9.311 -17.706,-9.477 -17.695,-9.573 -17.714,-9.748 -17.759,-9.818 -17.85,-9.771 -18.049,-9.646 -18.327,-9.463 -18.627,-9.258 -18.992,-9.012 -19.349,-8.783 -19.65,-8.599 -19.812,-8.509 -20.146,-8.312 -20.36,-8.101 -20.498,-7.817 -20.574,-7.535 -20.648,-7.247 -20.723,-7.009 -20.761,-6.914 -20.813,-6.757 -20.752,-6.718
  Top Layer region: -20.084,-0.057 -19.905,-0.214 -19.658,-0.445 -19.368,-0.727 -19.059,-1.036 -18.756,-1.348 -18.482,-1.639 -18.373,-1.76 -18.076,-2.093 -18.076,-2.952 -18.084,-3.35 -18.107,-3.637 -18.141,-3.789 -18.161,-3.808 -18.247,-3.744 -18.403,-3.573 -18.599,-3.329 -18.669,-3.237 -18.933,-2.906 -19.261,-2.527 -19.594,-2.169 -19.687,-2.074 -20.282,-1.482 -20.217,-1.058 -20.187,-0.734 -20.19,-0.417 -20.201,-0.318 -20.214,-0.112 -20.184,-0.005 -20.17,0
  Top Layer region: -20.446,-8.416 -20.276,-8.528 -20.053,-8.677 -19.739,-8.881 -19.387,-9.107 -19.219,-9.213 -18.834,-9.463 -18.431,-9.737 -18.079,-9.987 -17.979,-10.061 -17.706,-10.279 -17.544,-10.444 -17.461,-10.596 -17.427,-10.774 -17.427,-11.005 -17.49,-11.09 -17.503,-11.091 -17.603,-11.048 -17.611,-11.022 -17.682,-10.949 -17.874,-10.821 -18.156,-10.655 -18.495,-10.469 -18.859,-10.279 -19.217,-10.103 -19.536,-9.957 -19.755,-9.87 -20.009,-9.774 -20.173,-9.681 -20.289,-9.547 -20.4,-9.33 -20.496,-9.104 -20.654,-8.709 -20.733,-8.454 -20.727,-8.328 -20.633,-8.319
  Top Layer region: -20.045,-10.133 -19.835,-10.214 -19.532,-10.345 -19.166,-10.511 -18.765,-10.698 -18.358,-10.893 -17.976,-11.082 -17.646,-11.251 -17.398,-11.386 -17.261,-11.473 -17.245,-11.49 -17.191,-11.636 -17.149,-11.847 -17.126,-12.063 -17.129,-12.224 -17.155,-12.273 -17.265,-12.222 -17.442,-12.101 -17.484,-12.069 -17.671,-11.955 -17.971,-11.808 -18.336,-11.652 -18.584,-11.556 -18.956,-11.409 -19.283,-11.263 -19.522,-11.138 -19.614,-11.075 -19.757,-10.909 -19.907,-10.683 -20.037,-10.446 -20.123,-10.243 -20.139,-10.123 -20.134,-10.115
  Top Layer region: -19.763,-11.378 -19.523,-11.458 -19.157,-11.601 -18.674,-11.804 -18.089,-12.061 -17.968,-12.114 -17.717,-12.213 -17.51,-12.27 -17.454,-12.277 -17.393,-12.282 -17.323,-12.305 -17.225,-12.36 -17.081,-12.459 -16.873,-12.615 -16.584,-12.843 -16.194,-13.154 -15.825,-13.45 -15.484,-13.723 -15.179,-13.965 -14.94,-14.152 -14.798,-14.26 -14.786,-14.269 -14.659,-14.392 -14.681,-14.465 -14.837,-14.479 -15.078,-14.434 -15.272,-14.366 -15.515,-14.266 -15.588,-14.236 -15.995,-14.057 -16.465,-13.842 -16.966,-13.604 -17.058,-13.559 -17.542,-13.327 -17.979,-13.122 -18.346,-12.956 -18.618,-12.839 -18.77,-12.784 -18.787,-12.781 -18.914,-12.716 -19.094,-12.55 -19.301,-12.318 -19.508,-12.053 -19.69,-11.79 -19.82,-11.564 -19.873,-11.408 -19.861,-11.367 hole: -15.028,-14.224 -15.071,-14.266 -15.028,-14.309 -14.986,-14.266
  Top Layer region: 20.389,-11.373 20.385,-11.474 20.261,-11.684 20.023,-12.013 19.921,-12.148 19.673,-12.453 19.463,-12.671 19.315,-12.778 19.285,-12.785 19.163,-12.821 18.917,-12.923 18.576,-13.077 18.165,-13.273 17.758,-13.473 17.283,-13.707 16.829,-13.925 16.429,-14.109 16.119,-14.245 15.96,-14.308 15.688,-14.404 15.465,-14.487 15.388,-14.517 15.264,-14.53 15.24,-14.465 15.305,-14.329 15.388,-14.257 15.501,-14.173 15.719,-14 16.015,-13.76 16.364,-13.473 16.61,-13.268 16.992,-12.959 17.35,-12.685 17.655,-12.467 17.879,-12.327 17.965,-12.287 18.645,-12.055 19.388,-11.746 19.631,-11.636 20.017,-11.463 20.268,-11.373
  Top Layer region: 20.637,-10.215 20.568,-10.408 20.456,-10.643 20.324,-10.867 20.242,-10.98 20.105,-11.085 19.847,-11.228 19.506,-11.392 19.149,-11.544 18.756,-11.709 18.402,-11.871 18.127,-12.01 17.983,-12.099 17.756,-12.252 17.629,-12.27 17.593,-12.148 17.632,-11.917 17.734,-11.617 17.867,-11.387 18.005,-11.268 18.044,-11.261 18.14,-11.226 18.361,-11.129 18.679,-10.983 19.069,-10.8 19.354,-10.664 19.773,-10.467 20.137,-10.303 20.42,-10.183 20.596,-10.119 20.64,-10.113
  Top Layer region: 21.336,-8.378 21.303,-8.498 21.217,-8.722 21.099,-9.004 20.969,-9.295 20.846,-9.547 20.836,-9.567 20.725,-9.662 20.504,-9.779 20.269,-9.876 19.989,-9.995 19.618,-10.177 19.209,-10.395 18.895,-10.574 18.553,-10.774 18.266,-10.939 18.066,-11.05 17.98,-11.091 17.98,-11.091 17.96,-11.017 17.961,-10.832 17.965,-10.774 17.993,-10.607 18.062,-10.466 18.201,-10.315 18.44,-10.119 18.584,-10.008 18.855,-9.812 19.205,-9.572 19.6,-9.308 20.012,-9.041 20.408,-8.79 20.759,-8.575 21.031,-8.416 21.196,-8.333 21.196,-8.333 21.314,-8.331
  Top Layer region: 20.71,-0.1 20.73,-0.327 20.745,-0.64 20.75,-0.781 20.767,-1.517 20.141,-2.183 19.83,-2.521 19.515,-2.876 19.243,-3.193 19.135,-3.325 18.937,-3.56 18.772,-3.731 18.673,-3.805 18.669,-3.806 18.63,-3.727 18.601,-3.502 18.586,-3.153 18.584,-2.942 18.584,-2.074 19.615,-1.016 19.951,-0.676 20.247,-0.386 20.481,-0.165 20.636,-0.032 20.689,-0.002
  Top Layer region: 21.331,-6.755 21.316,-6.922 21.232,-7.151 21.211,-7.192 21.113,-7.443 21.039,-7.735 21.034,-7.766 20.994,-7.94 20.919,-8.075 20.777,-8.207 20.534,-8.371 20.375,-8.469 20.024,-8.688 19.604,-8.956 19.186,-9.228 19.032,-9.33 18.723,-9.533 18.469,-9.695 18.3,-9.797 18.249,-9.821 18.216,-9.748 18.203,-9.577 18.229,-9.441 18.318,-9.282 18.49,-9.073 18.764,-8.79 18.902,-8.654 19.184,-8.389 19.52,-8.089 19.883,-7.774 20.249,-7.465 20.594,-7.183 20.893,-6.947 21.122,-6.778 21.256,-6.696 21.273,-6.691
  Top Layer region: 21.181,-3.582 21.184,-3.687 21.128,-3.905 21.113,-3.958 21.043,-4.259 21.011,-4.543 21.013,-4.632 21.011,-4.737 20.977,-4.847 20.897,-4.981 20.753,-5.159 20.532,-5.401 20.217,-5.726 19.894,-6.053 19.537,-6.415 19.222,-6.739 18.97,-7.005 18.798,-7.193 18.726,-7.282 18.725,-7.284 18.629,-7.362 18.598,-7.366 18.539,-7.286 18.512,-7.045 18.512,-6.817 18.525,-6.267 19.697,-5.03 20.059,-4.647 20.382,-4.3 20.648,-4.009 20.838,-3.797 20.933,-3.683 20.938,-3.675 21.061,-3.569 21.12,-3.556
  Top Layer region: 21.166,-1.75 21.18,-1.932 21.147,-2.253 21.112,-2.576 21.095,-2.858 21.098,-3.019 21.087,-3.112 21.022,-3.237 20.891,-3.411 20.68,-3.65 20.374,-3.97 19.961,-4.388 19.9,-4.449 19.529,-4.818 19.198,-5.142 18.927,-5.404 18.734,-5.586 18.637,-5.669 18.63,-5.673 18.608,-5.595 18.592,-5.389 18.585,-5.095 18.584,-5.02 18.584,-4.366 19.483,-3.432 19.829,-3.069 20.161,-2.713 20.449,-2.399 20.662,-2.159 20.711,-2.101 20.942,-1.838 21.09,-1.72
  Top Layer region: 21.429,-5.014 21.395,-5.225 21.324,-5.521 21.283,-5.673 21.189,-5.989 21.1,-6.223 20.99,-6.419 20.83,-6.617 20.594,-6.861 20.381,-7.07 20.003,-7.434 19.621,-7.795 19.255,-8.133 18.927,-8.431 18.658,-8.669 18.468,-8.828 18.377,-8.89 18.376,-8.89 18.357,-8.814 18.358,-8.618 18.372,-8.437 18.39,-8.276 18.422,-8.138 18.483,-8 18.59,-7.839 18.758,-7.634 19.004,-7.36 19.344,-6.996 19.516,-6.813 20.036,-6.26 20.453,-5.821 20.778,-5.484 21.023,-5.238 21.199,-5.071 21.317,-4.972 21.39,-4.929 21.42,-4.927
  Top Layer region: 22.521,-11.808 22.468,-11.885 22.326,-12.051 22.125,-12.274 22.086,-12.316 21.65,-12.785 20.816,-12.785 20.463,-12.778 20.184,-12.762 20.015,-12.737 19.981,-12.719 20.059,-12.524 20.261,-12.359 20.545,-12.258 20.592,-12.251 20.854,-12.198 21.203,-12.106 21.566,-11.993 21.59,-11.985 22.027,-11.848 22.331,-11.778 22.494,-11.776
  Top Layer region: 23.427,-10.276 23.399,-10.357 23.286,-10.538 23.109,-10.786 23.017,-10.907 22.792,-11.193 22.617,-11.378 22.445,-11.497 22.225,-11.587 21.929,-11.676 21.495,-11.789 21.105,-11.871 20.789,-11.918 20.575,-11.926 20.493,-11.89 20.493,-11.886 20.531,-11.767 20.62,-11.569 20.642,-11.526 20.732,-11.38 20.855,-11.263 21.043,-11.157 21.326,-11.046 21.735,-10.913 21.844,-10.88 22.519,-10.648 23.063,-10.403 23.101,-10.383 23.293,-10.296 23.415,-10.27
  Top Layer region: 23.548,2.716 23.549,2.506 23.536,2.202 23.524,2.011 23.499,1.65 23.477,1.342 23.464,1.135 23.461,1.086 23.395,0.971 23.204,0.747 22.887,0.412 22.444,-0.033 21.875,-0.588 21.407,-1.037 21.258,-1.151 21.17,-1.185 21.132,-1.107 21.097,-0.897 21.089,-0.804 21.072,-0.593 21.064,-0.42 21.04,0.346 22.264,1.57 22.635,1.939 22.966,2.263 23.237,2.525 23.43,2.707 23.527,2.791 23.534,2.794 hole: 21.463,-0.762 21.421,-0.804 21.463,-0.847 21.505,-0.804
  Top Layer region: 23.875,-8.841 23.876,-8.854 23.833,-8.963 23.722,-9.169 23.569,-9.429 23.401,-9.7 23.244,-9.938 23.125,-10.101 23.086,-10.141 22.974,-10.195 22.74,-10.289 22.423,-10.409 22.061,-10.54 21.693,-10.671 21.355,-10.787 21.087,-10.874 20.927,-10.919 20.904,-10.922 20.832,-10.869 20.831,-10.858 20.871,-10.745 20.955,-10.583 21.049,-10.341 21.079,-10.149 21.092,-10.013 21.144,-9.905 21.264,-9.806 21.477,-9.694 21.811,-9.55 21.971,-9.485 22.573,-9.241 23.035,-9.058 23.377,-8.929 23.614,-8.848 23.765,-8.811 23.846,-8.81
  Top Layer region: 24.204,1.025 24.216,0.827 24.2,0.549 24.16,0.233 24.101,-0.08 24.028,-0.345 23.974,-0.476 23.836,-0.674 23.605,-0.937 23.319,-1.224 23.141,-1.386 22.794,-1.695 22.43,-2.025 22.109,-2.321 22,-2.423 21.762,-2.639 21.563,-2.8 21.441,-2.876 21.429,-2.879 21.378,-2.796 21.347,-2.556 21.336,-2.167 21.336,-1.452 22.458,-0.439 22.841,-0.091 23.197,0.237 23.501,0.52 23.726,0.734 23.828,0.837 23.999,1 24.131,1.093 24.158,1.101
  Top Layer region: 24.289,-6.894 24.299,-6.935 24.265,-7.062 24.176,-7.296 24.052,-7.593 23.912,-7.909 23.775,-8.2 23.663,-8.421 23.596,-8.525 23.487,-8.587 23.257,-8.693 22.943,-8.827 22.583,-8.974 22.215,-9.12 21.876,-9.248 21.604,-9.345 21.438,-9.395 21.412,-9.398 21.349,-9.328 21.338,-9.25 21.366,-9.097 21.436,-8.842 21.529,-8.551 21.717,-8.001 22.86,-7.432 23.382,-7.178 23.772,-7.002 24.043,-6.899 24.211,-6.865
  Top Layer region: 24.528,-4.772 24.539,-4.886 24.493,-5.108 24.405,-5.393 24.29,-5.696 24.163,-5.971 24.08,-6.115 23.956,-6.325 23.883,-6.48 23.876,-6.513 23.798,-6.637 23.564,-6.822 23.178,-7.067 22.64,-7.37 22.43,-7.483 21.991,-7.711 21.681,-7.861 21.481,-7.938 21.372,-7.95 21.338,-7.903 21.338,-7.895 21.364,-7.791 21.432,-7.567 21.528,-7.262 21.577,-7.112 21.812,-6.392 22.434,-5.962 22.772,-5.736 23.112,-5.521 23.393,-5.358 23.445,-5.33 23.752,-5.162 24.06,-4.981 24.153,-4.922 24.356,-4.81 24.498,-4.765
  Top Layer region: 24.554,-0.668 24.561,-0.863 24.539,-1.135 24.492,-1.439 24.425,-1.732 24.37,-1.905 24.291,-2.093 24.202,-2.256 24.082,-2.416 23.91,-2.59 23.668,-2.799 23.334,-3.063 22.889,-3.401 22.739,-3.514 22.313,-3.833 22.002,-4.062 21.788,-4.21 21.649,-4.29 21.565,-4.31 21.517,-4.282 21.485,-4.217 21.472,-4.184 21.44,-4.018 21.422,-3.767 21.421,-3.686 21.428,-3.522 21.463,-3.383 21.548,-3.24 21.704,-3.059 21.951,-2.81 22.119,-2.647 22.389,-2.392 22.713,-2.097 23.068,-1.782 23.43,-1.467 23.774,-1.172 24.079,-0.918 24.319,-0.725 24.472,-0.613 24.512,-0.593
  Top Layer region: 24.698,-2.488 24.705,-2.595 24.661,-2.82 24.579,-3.123 24.472,-3.463 24.351,-3.801 24.229,-4.097 24.155,-4.248 24.047,-4.421 23.907,-4.585 23.709,-4.763 23.427,-4.976 23.035,-5.246 22.851,-5.37 22.473,-5.62 22.146,-5.832 21.896,-5.992 21.747,-6.082 21.718,-6.096 21.688,-6.022 21.675,-5.844 21.675,-5.839 21.701,-5.623 21.769,-5.319 21.851,-5.036 21.95,-4.759 22.064,-4.543 22.225,-4.34 22.467,-4.103 22.634,-3.954 22.95,-3.686 23.3,-3.407 23.66,-3.135 24.004,-2.888 24.305,-2.685 24.537,-2.544 24.675,-2.484
  Top Layer region: 25.157,-11.472 25.223,-11.539 25.231,-11.591 25.154,-11.777 24.945,-11.994 24.633,-12.221 24.249,-12.442 23.821,-12.639 23.38,-12.793 23.114,-12.86 22.778,-12.911 22.452,-12.932 22.177,-12.922 21.994,-12.884 21.939,-12.827 22.002,-12.736 22.162,-12.561 22.391,-12.332 22.534,-12.196 23.118,-11.651 23.857,-11.546 24.38,-11.477 24.757,-11.441 25.009,-11.439
  Top Layer region: 25.882,-9.616 25.894,-9.76 25.771,-9.993 25.517,-10.312 25.377,-10.465 25.119,-10.732 24.924,-10.905 24.737,-11.016 24.505,-11.095 24.176,-11.173 24.128,-11.183 23.688,-11.276 23.39,-11.326 23.21,-11.337 23.127,-11.31 23.114,-11.275 23.162,-11.156 23.288,-10.947 23.462,-10.693 23.654,-10.434 23.835,-10.216 23.853,-10.196 24.02,-10.049 24.238,-9.933 24.551,-9.826 24.828,-9.752 25.179,-9.668 25.483,-9.605 25.691,-9.571 25.736,-9.567
  Top Layer region: 26.918,-7.796 27.008,-7.831 27.009,-7.836 26.943,-8.028 26.764,-8.278 26.501,-8.55 26.268,-8.745 25.998,-8.949 25.779,-9.1 25.568,-9.221 25.323,-9.333 25.001,-9.459 24.594,-9.608 24.178,-9.756 23.897,-9.85 23.726,-9.895 23.643,-9.898 23.622,-9.869 23.674,-9.79 23.805,-9.633 23.875,-9.554 24.062,-9.303 24.205,-9.033 24.225,-8.978 24.311,-8.75 24.394,-8.588 24.403,-8.575 24.542,-8.469 24.797,-8.33 25.122,-8.18 25.473,-8.038 25.805,-7.925 25.866,-7.908 26.14,-7.848 26.437,-7.808 26.712,-7.79
  Top Layer region: 27.056,6.016 27.088,5.789 27.093,5.586 27.082,5.322 27.039,5.083 26.949,4.82 26.796,4.483 26.703,4.295 26.554,4.007 26.412,3.764 26.254,3.538 26.057,3.302 25.798,3.025 25.455,2.681 25.158,2.392 24.793,2.041 24.467,1.735 24.199,1.493 24.01,1.331 23.92,1.27 23.919,1.27 23.881,1.352 23.856,1.586 23.847,1.956 23.849,2.214 23.864,3.157 24.97,4.401 25.455,4.935 25.851,5.344 26.168,5.638 26.417,5.827 26.49,5.87 26.735,5.995 26.927,6.077 26.999,6.096
  Top Layer region: 27.311,-5.855 27.397,-5.938 27.357,-6.089 27.191,-6.32 26.899,-6.648 26.808,-6.746 26.241,-7.28 25.65,-7.692 24.976,-8.017 24.646,-8.139 24.335,-8.242 24.152,-8.288 24.066,-8.282 24.046,-8.234 24.086,-8.129 24.185,-7.933 24.258,-7.802 24.381,-7.565 24.457,-7.376 24.469,-7.317 24.499,-7.168 24.573,-6.942 24.599,-6.875 24.682,-6.707 24.801,-6.569 24.992,-6.433 25.291,-6.269 25.424,-6.201 25.797,-6.023 26.09,-5.914 26.37,-5.855 26.701,-5.828 26.752,-5.825 27.096,-5.822
  Top Layer region: 27.686,3.736 27.74,3.545 27.743,3.288 27.702,3.067 27.504,2.446 27.289,1.96 27.035,1.574 26.723,1.252 26.56,1.121 26.045,0.735 25.569,0.384 25.151,0.08 24.807,-0.163 24.556,-0.332 24.415,-0.416 24.395,-0.423 24.379,-0.347 24.396,-0.142 24.444,0.153 24.476,0.318 24.547,0.68 24.602,1.005 24.632,1.238 24.635,1.288 24.668,1.439 24.783,1.59 25.007,1.776 25.125,1.861 25.577,2.185 25.951,2.468 26.306,2.758 26.702,3.102 26.861,3.244 27.138,3.483 27.373,3.673 27.536,3.787 27.588,3.81
  Top Layer region: 27.72,-3.347 27.793,-3.466 27.763,-3.691 27.638,-4.024 27.513,-4.292 27.286,-4.67 26.981,-5.015 26.576,-5.346 26.049,-5.681 25.454,-6.001 25.024,-6.214 24.722,-6.35 24.528,-6.417 24.422,-6.419 24.385,-6.365 24.384,-6.347 24.42,-6.224 24.511,-6.014 24.566,-5.902 24.692,-5.626 24.832,-5.273 24.93,-4.995 25.113,-4.445 26.244,-3.869 26.806,-3.594 27.235,-3.413 27.537,-3.33
  Top Layer region: 27.823,-0.852 27.985,-0.91 28.025,-0.99 27.978,-1.153 27.853,-1.412 27.674,-1.727 27.466,-2.059 27.251,-2.368 27.054,-2.615 27.019,-2.653 26.698,-2.966 26.341,-3.273 25.969,-3.56 25.603,-3.812 25.267,-4.017 24.982,-4.159 24.77,-4.225 24.654,-4.202 24.638,-4.152 24.667,-4.031 24.741,-3.814 24.799,-3.662 24.907,-3.324 24.994,-2.941 25.019,-2.783 25.061,-2.509 25.106,-2.302 25.133,-2.23 25.229,-2.147 25.437,-1.998 25.721,-1.807 26.048,-1.594 26.383,-1.382 26.693,-1.194 26.944,-1.05 27.007,-1.017 27.291,-0.907 27.578,-0.851
  Top Layer region: 28.15,1.234 28.193,1.156 28.194,1.133 28.139,0.938 27.99,0.659 27.773,0.334 27.514,-0.002 27.237,-0.31 27.108,-0.437 26.894,-0.619 26.602,-0.849 26.26,-1.107 25.896,-1.372 25.538,-1.624 25.215,-1.844 24.955,-2.01 24.786,-2.104 24.744,-2.117 24.724,-2.039 24.722,-1.829 24.739,-1.523 24.757,-1.303 24.836,-0.49 25.348,-0.065 26.021,0.46 26.612,0.847 27.118,1.094 27.422,1.184 27.792,1.246 28.026,1.264
XZDGK45WT-9 [mm] "Reverse Mount SMD LED"
  rect 1.4x2.6 smd: 1(-2.6,0) 2(2.6,0)
  Top Layer keep-out region: -1.625,1.4 1.625,1.4 1.625,-1.4 -1.625,-1.4
  silkscreen extent -4.31,-1.55 1.5,1.55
